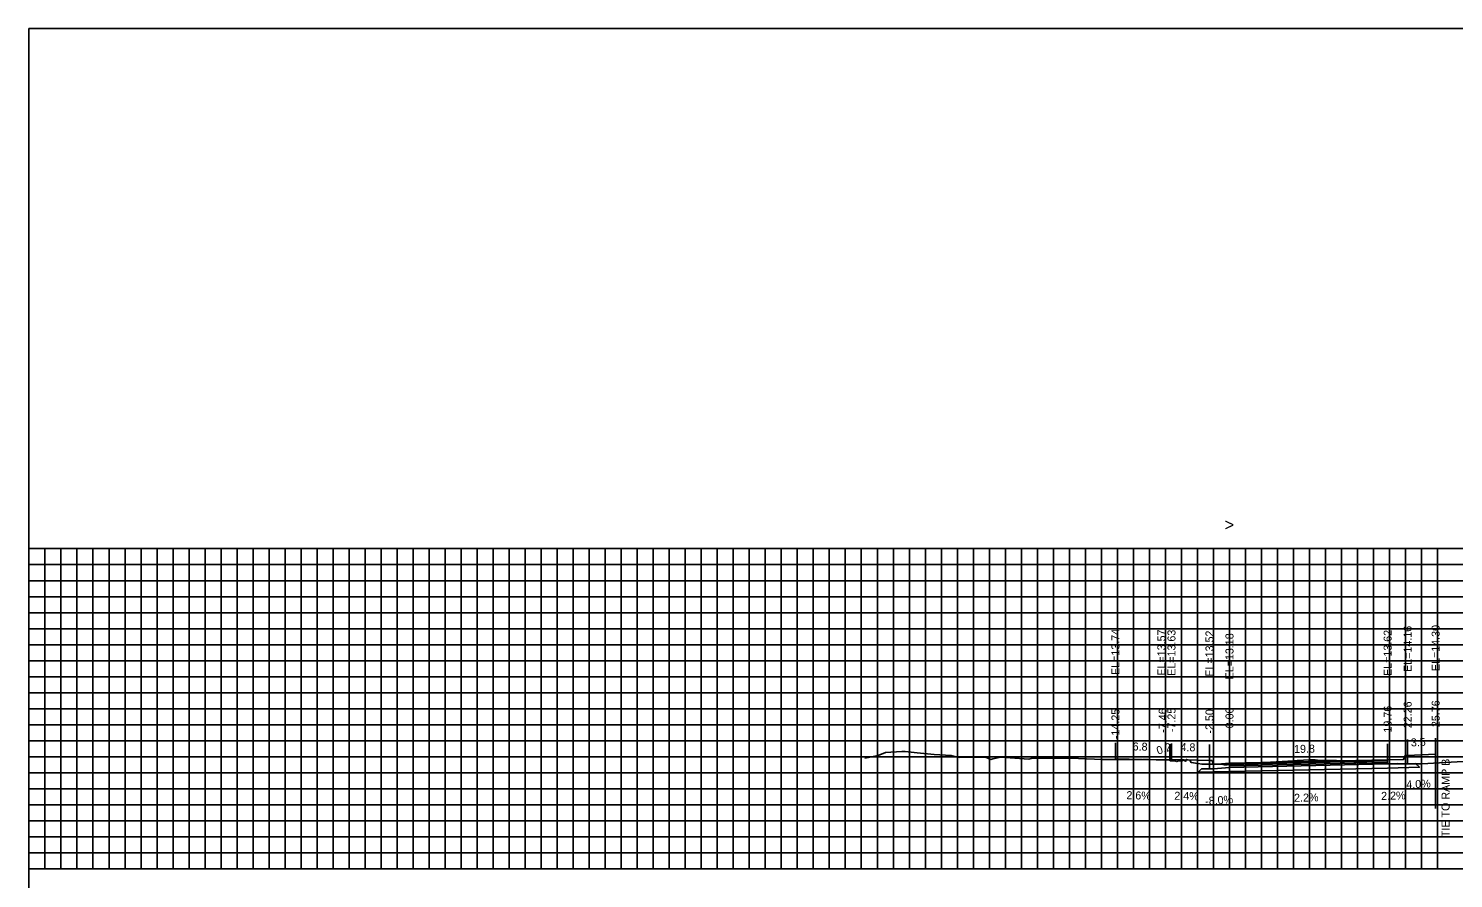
# Model space of a CAD drawing. Extents: x 1797645 to 1803805, y 248417 to 250269.
# Drawn here: x 1802140.9 to 1802319, y 250163.2 to 250269.4 of the extents above; entities that cross this region are included whole.
import ezdxf

# ---------------------------------------------------------------- set-up
doc = ezdxf.new("R2010")
doc.units = 0
for name, color, linetype in [('3', 7, 'Continuous'), ('4', 7, 'Continuous'), ('60', 7, 'Continuous'), ('BASE', 7, 'Continuous'), ('CL-CNST', 7, 'Continuous'), ('Level 62', 7, 'Continuous'), ('LOWER BINDER', 7, 'Continuous'), ('M-ROADS', 7, 'Continuous'), ('UPPER BINDER', 7, 'Continuous'), ('WEARING', 7, 'Continuous')]:
    doc.layers.add(name, color=color, linetype=linetype)

msp = doc.modelspace()

# ---------------------------------------------------------------- linework, layer by layer
for p, q in [((1802276.75, 250178.17), (1802276.75, 250180.17)), ((1802283.55, 250178), (1802283.55, 250180)), ((1802283.75, 250178.07), (1802283.75, 250180.07)), ((1802288.5, 250177.95), (1802288.5, 250179.95)), ((1802291, 250177.61), (1802291, 250179.61)), ((1802310.76, 250178.05), (1802310.76, 250180.05)), ((1802313.26, 250178.59), (1802313.26, 250180.59)), ((1802316.76, 250178.73), (1802316.76, 250180.73))]:
    msp.add_line(p, q)
for points in [[(1802141, 250079.43), (1802441, 250079.43), (1802441, 250269.43), (1802141, 250269.43)], [(1802291, 250177.61), (1802289, 250177.45), (1802288.83, 250177.95), (1802288.5, 250177.95), (1802288.5, 250176.92), (1802289, 250176.92), (1802291, 250177.08)], [(1802310.76, 250178.05), (1802312.76, 250178.09), (1802312.93, 250178.59), (1802313.26, 250178.59), (1802313.26, 250177.56), (1802312.76, 250177.56), (1802310.76, 250177.52)]]:
    msp.add_lwpolyline(points, close=True)
at = {"layer": '3'}
msp.add_line((1802316.76, 250178.73), (1802316.76, 250171.95), dxfattribs=at)
at = {"layer": '60'}
for p, q in [((1802140.94, 250204.43), (1802141, 250204.43)), ((1802141, 250164.43), (1802141, 250204.43)), ((1802140.94, 250194.43), (1802141, 250194.43)), ((1802140.94, 250184.43), (1802141, 250184.43)), ((1802140.94, 250174.43), (1802141, 250174.43)), ((1802140.94, 250164.43), (1802141, 250164.43)), ((1802141, 250164.43), (1802441, 250164.43)), ((1802141, 250164.37), (1802141, 250164.43)), ((1802151, 250164.37), (1802151, 250164.43)), ((1802161, 250164.37), (1802161, 250164.43)), ((1802171, 250164.37), (1802171, 250164.43)), ((1802181, 250164.37), (1802181, 250164.43)), ((1802191, 250164.37), (1802191, 250164.43)), ((1802201, 250164.37), (1802201, 250164.43)), ((1802211, 250164.37), (1802211, 250164.43)), ((1802221, 250164.37), (1802221, 250164.43)), ((1802231, 250164.37), (1802231, 250164.43)), ((1802241, 250164.37), (1802241, 250164.43)), ((1802251, 250164.37), (1802251, 250164.43)), ((1802261, 250164.37), (1802261, 250164.43)), ((1802271, 250164.37), (1802271, 250164.43)), ((1802281, 250164.37), (1802281, 250164.43)), ((1802291, 250164.37), (1802291, 250164.43)), ((1802301, 250164.37), (1802301, 250164.43)), ((1802311, 250164.37), (1802311, 250164.43))]:
    msp.add_line(p, q, dxfattribs=at)
at = {"layer": 'BASE'}
msp.add_lwpolyline([(1802291, 250177.08), (1802310.76, 250177.52), (1802312.76, 250177.56), (1802313.26, 250177.56), (1802314.26, 250177.58), (1802314.74, 250177.11), (1802310.76, 250177.02), (1802291, 250176.58), (1802287.09, 250176.5), (1802287.5, 250176.9), (1802288.5, 250176.92), (1802289, 250176.92)], close=True, dxfattribs=at)
at = {"layer": 'CL-CNST'}
msp.add_lwpolyline([(1802276.75, 250178.17), (1802283.55, 250178), (1802283.75, 250178.07), (1802288.5, 250177.95), (1802288.83, 250177.95), (1802289, 250177.45), (1802291, 250177.61), (1802310.76, 250178.05), (1802312.76, 250178.09), (1802312.93, 250178.59), (1802313.26, 250178.59), (1802316.76, 250178.73)], dxfattribs=at)
at = {"layer": 'Level 62'}
for p, q in [((1802141, 250204.43), (1802441, 250204.43)), ((1802141, 250164.43), (1802141, 250204.43)), ((1802143, 250164.43), (1802143, 250204.43)), ((1802145, 250164.43), (1802145, 250204.43)), ((1802147, 250164.43), (1802147, 250204.43)), ((1802149, 250164.43), (1802149, 250204.43)), ((1802151, 250164.43), (1802151, 250204.43)), ((1802153, 250164.43), (1802153, 250204.43)), ((1802155, 250164.43), (1802155, 250204.43)), ((1802157, 250164.43), (1802157, 250204.43)), ((1802159, 250164.43), (1802159, 250204.43)), ((1802161, 250164.43), (1802161, 250204.43)), ((1802163, 250164.43), (1802163, 250204.43)), ((1802165, 250164.43), (1802165, 250204.43)), ((1802167, 250164.43), (1802167, 250204.43)), ((1802169, 250164.43), (1802169, 250204.43)), ((1802171, 250164.43), (1802171, 250204.43)), ((1802173, 250164.43), (1802173, 250204.43)), ((1802175, 250164.43), (1802175, 250204.43)), ((1802177, 250164.43), (1802177, 250204.43)), ((1802179, 250164.43), (1802179, 250204.43)), ((1802181, 250164.43), (1802181, 250204.43)), ((1802183, 250164.43), (1802183, 250204.43)), ((1802185, 250164.43), (1802185, 250204.43)), ((1802187, 250164.43), (1802187, 250204.43)), ((1802189, 250164.43), (1802189, 250204.43)), ((1802191, 250164.43), (1802191, 250204.43)), ((1802193, 250164.43), (1802193, 250204.43)), ((1802195, 250164.43), (1802195, 250204.43)), ((1802197, 250164.43), (1802197, 250204.43)), ((1802199, 250164.43), (1802199, 250204.43)), ((1802201, 250164.43), (1802201, 250204.43)), ((1802203, 250164.43), (1802203, 250204.43)), ((1802205, 250164.43), (1802205, 250204.43)), ((1802207, 250164.43), (1802207, 250204.43)), ((1802209, 250164.43), (1802209, 250204.43)), ((1802211, 250164.43), (1802211, 250204.43)), ((1802213, 250164.43), (1802213, 250204.43)), ((1802215, 250164.43), (1802215, 250204.43)), ((1802217, 250164.43), (1802217, 250204.43)), ((1802219, 250164.43), (1802219, 250204.43)), ((1802221, 250164.43), (1802221, 250204.43)), ((1802223, 250164.43), (1802223, 250204.43)), ((1802225, 250164.43), (1802225, 250204.43)), ((1802227, 250164.43), (1802227, 250204.43)), ((1802229, 250164.43), (1802229, 250204.43)), ((1802231, 250164.43), (1802231, 250204.43)), ((1802233, 250164.43), (1802233, 250204.43)), ((1802235, 250164.43), (1802235, 250204.43)), ((1802237, 250164.43), (1802237, 250204.43)), ((1802239, 250164.43), (1802239, 250204.43)), ((1802241, 250164.43), (1802241, 250204.43)), ((1802243, 250164.43), (1802243, 250204.43)), ((1802245, 250164.43), (1802245, 250204.43)), ((1802247, 250164.43), (1802247, 250204.43)), ((1802249, 250164.43), (1802249, 250204.43)), ((1802251, 250164.43), (1802251, 250204.43)), ((1802253, 250164.43), (1802253, 250204.43)), ((1802255, 250164.43), (1802255, 250204.43)), ((1802257, 250164.43), (1802257, 250204.43)), ((1802259, 250164.43), (1802259, 250204.43)), ((1802261, 250164.43), (1802261, 250204.43)), ((1802263, 250164.43), (1802263, 250204.43)), ((1802265, 250164.43), (1802265, 250204.43)), ((1802267, 250164.43), (1802267, 250204.43)), ((1802269, 250164.43), (1802269, 250204.43)), ((1802271, 250164.43), (1802271, 250204.43)), ((1802273, 250164.43), (1802273, 250204.43)), ((1802275, 250164.43), (1802275, 250204.43)), ((1802277, 250164.43), (1802277, 250204.43)), ((1802279, 250164.43), (1802279, 250204.43)), ((1802281, 250164.43), (1802281, 250204.43)), ((1802283, 250164.43), (1802283, 250204.43)), ((1802285, 250164.43), (1802285, 250204.43)), ((1802287, 250164.43), (1802287, 250204.43)), ((1802289, 250164.43), (1802289, 250204.43)), ((1802291, 250164.43), (1802291, 250204.43)), ((1802293, 250164.43), (1802293, 250204.43)), ((1802295, 250164.43), (1802295, 250204.43)), ((1802297, 250164.43), (1802297, 250204.43)), ((1802299, 250164.43), (1802299, 250204.43)), ((1802301, 250164.43), (1802301, 250204.43)), ((1802303, 250164.43), (1802303, 250204.43)), ((1802305, 250164.43), (1802305, 250204.43)), ((1802307, 250164.43), (1802307, 250204.43)), ((1802309, 250164.43), (1802309, 250204.43)), ((1802311, 250164.43), (1802311, 250204.43)), ((1802313, 250164.43), (1802313, 250204.43)), ((1802315, 250164.43), (1802315, 250204.43)), ((1802317, 250164.43), (1802317, 250204.43)), ((1802141, 250202.43), (1802441, 250202.43)), ((1802141, 250200.43), (1802441, 250200.43)), ((1802141, 250198.43), (1802441, 250198.43)), ((1802141, 250196.43), (1802441, 250196.43)), ((1802141, 250194.43), (1802441, 250194.43)), ((1802141, 250192.43), (1802441, 250192.43)), ((1802141, 250190.43), (1802441, 250190.43)), ((1802141, 250188.43), (1802441, 250188.43)), ((1802141, 250186.43), (1802441, 250186.43)), ((1802141, 250184.43), (1802441, 250184.43)), ((1802141, 250182.43), (1802441, 250182.43)), ((1802141, 250180.43), (1802441, 250180.43)), ((1802141, 250178.43), (1802441, 250178.43)), ((1802141, 250176.43), (1802441, 250176.43)), ((1802141, 250174.43), (1802441, 250174.43)), ((1802141, 250172.43), (1802441, 250172.43)), ((1802141, 250170.43), (1802441, 250170.43)), ((1802141, 250168.43), (1802441, 250168.43)), ((1802141, 250166.43), (1802441, 250166.43)), ((1802141, 250164.43), (1802441, 250164.43))]:
    msp.add_line(p, q, dxfattribs=at)
at = {"layer": 'LOWER BINDER'}
msp.add_lwpolyline([(1802310.76, 250177.52), (1802310.76, 250177.52), (1802310.76, 250177.71), (1802291, 250177.27), (1802291, 250177.08)], close=True, dxfattribs=at)
at = {"layer": 'M-ROADS'}
msp.add_lwpolyline([(1802245.45, 250178.26), (1802245.86, 250178.32), (1802247.11, 250178.59), (1802248.03, 250178.96), (1802250.08, 250179.1), (1802250.24, 250179.1), (1802250.46, 250179.1), (1802251.97, 250178.93), (1802254.08, 250178.7), (1802256.24, 250178.6), (1802257.28, 250178.33), (1802258.76, 250178.38), (1802260.28, 250178.38), (1802260.45, 250178.37), (1802260.51, 250178.36), (1802261.16, 250178.09), (1802261.45, 250178.18), (1802262.44, 250178.37), (1802265.91, 250178.12), (1802266.23, 250178.21), (1802268.79, 250178.25), (1802270.01, 250178.26), (1802271.14, 250178.26), (1802275.14, 250178.1), (1802275.39, 250178.09), (1802275.56, 250178.08), (1802276.84, 250178.07), (1802277.5, 250178.09), (1802277.94, 250178.08), (1802278.11, 250178.08), (1802278.58, 250178.07), (1802278.59, 250178.07), (1802278.92, 250178.02), (1802280.22, 250178.08), (1802280.69, 250178.08), (1802280.83, 250178.09), (1802283.47, 250178.06), (1802283.64, 250177.92), (1802283.72, 250177.91), (1802283.99, 250177.93), (1802284.13, 250177.93), (1802284.29, 250177.93), (1802284.29, 250177.88), (1802284.44, 250177.83), (1802284.61, 250177.92), (1802284.81, 250177.9), (1802284.95, 250177.88), (1802285.29, 250178), (1802285.47, 250177.9), (1802285.49, 250177.85), (1802285.6, 250178.07), (1802285.65, 250178.08), (1802286.05, 250178), (1802286.2, 250177.71), (1802287.06, 250177.6), (1802287.57, 250177.48), (1802287.58, 250177.48), (1802287.6, 250177.48), (1802289.96, 250177.49), (1802290.33, 250177.43), (1802290.41, 250177.41), (1802290.69, 250177.42), (1802292.53, 250177.49), (1802293.91, 250177.62), (1802299.04, 250177.92), (1802299.44, 250177.94), (1802299.57, 250177.96), (1802300.91, 250178.05), (1802301.7, 250178.04), (1802301.97, 250178), (1802302.14, 250177.94), (1802302.71, 250177.94), (1802304.39, 250177.94), (1802309.26, 250177.6), (1802309.92, 250177.55), (1802310.15, 250177.56), (1802312.03, 250177.57), (1802312.33, 250177.55), (1802312.58, 250177.55), (1802313.3, 250177.55), (1802314.86, 250177.56), (1802315.78, 250177.6), (1802317.93, 250177.7), (1802322.45, 250177.96)], dxfattribs=at)
at = {"layer": 'UPPER BINDER'}
msp.add_lwpolyline([(1802310.76, 250177.71), (1802310.76, 250177.9), (1802291, 250177.46), (1802291, 250177.27)], close=True, dxfattribs=at)
at = {"layer": 'WEARING'}
msp.add_lwpolyline([(1802310.76, 250177.9), (1802310.76, 250178.05), (1802291, 250177.61), (1802291, 250177.46)], close=True, dxfattribs=at)

# ---------------------------------------------------------------- texts
at = {"layer": '3'}
for s, p in [('EL=13.74', (1802277.25, 250188.64)), ('EL=13.57', (1802282.99, 250188.56)), ('EL=13.63', (1802284.25, 250188.54)), ('EL=13.52', (1802289, 250188.43)), ('EL=13.18', (1802291.5, 250188.09)), ('EL=13.62', (1802311.26, 250188.52)), ('EL=14.16', (1802313.76, 250189.02)), ('EL=14.30', (1802317.26, 250189.13)), ('22.26', (1802313.76, 250181.99)), ('25.76', (1802317.26, 250182.13)), ('-14.25', (1802277.25, 250180.63)), ('-7.46', (1802283.15, 250181.43)), ('-7.25', (1802284.25, 250181.51)), ('-2.50', (1802289, 250181.32)), ('0.00', (1802291.5, 250181.98)), ('19.76', (1802311.26, 250181.45)), ('TIE TO RAMP B', (1802318.5, 250168.38))]:
    msp.add_text(s, height=1, rotation=90, dxfattribs=at).set_placement(p)
at = {"layer": '4'}
for s, rotation, p in [('6.8', 358.536, (1802278.89, 250179.22)), ('0.2', 18.4349, (1802282.08, 250178.67)), ('4.8', 358.6512, (1802284.87, 250179.14)), ('19.8', 1.2603, (1802299.08, 250178.89)), ('3.5', 2.2906, (1802313.68, 250179.71)), ('4.0%', 2.2906, (1802313.11, 250174.47)), ('2.6%', 358.536, (1802278.11, 250173.13)), ('2.4%', 358.6512, (1802284.1, 250173.06)), ('-8.0%', 4.5739, (1802288, 250172.36)), ('2.2%', 1.2603, (1802299.08, 250172.79)), ('2.2%', 1.2603, (1802309.96, 250173.03))]:
    msp.add_text(s, height=1, rotation=rotation, dxfattribs=at).set_placement(p)
at = {"layer": '60'}
for s, height, p in [('>', 1.5, (1802290.39, 250206.68)), ('-', 0.0001, (1802141, 250164.43))]:
    msp.add_text(s, height=height, dxfattribs=at).set_placement(p)

doc.saveas('drawing.dxf')
